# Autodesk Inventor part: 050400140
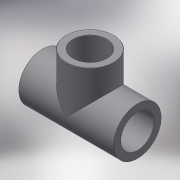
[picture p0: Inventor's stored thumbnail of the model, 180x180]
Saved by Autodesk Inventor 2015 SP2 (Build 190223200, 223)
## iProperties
Created: 2017-10
Part Number: 050400140
Material: Generic
Description: PLASSON TEE-CEMENT PVC 140
Document SubType Name: Modeling
Designer: KIM
Density: 1 g/cm^3
Appearance: Default
Author: KIM
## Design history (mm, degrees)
derived "050400.ipt"
feature "Solid1::050400.ipt"
feature "Solid2::050400.ipt"
tag "TaggingFeature1"
body "Solid1"
other parameters: "d0" = 298, "d1" = 162, "d2" = 76, "d5" = 126, "d7" = 1.4, "d8" = 76, "d9" = 149, "d10" = 162, "d12" = 126, "d15" = 0, "d17" = 0, "d19" = 126, "d21" = 76, "d22" = 0, "d23" = 76, "d24" = 1.4, "E_" = 162, "H_" = 298, "l_" = 76, "Z_" = 73
